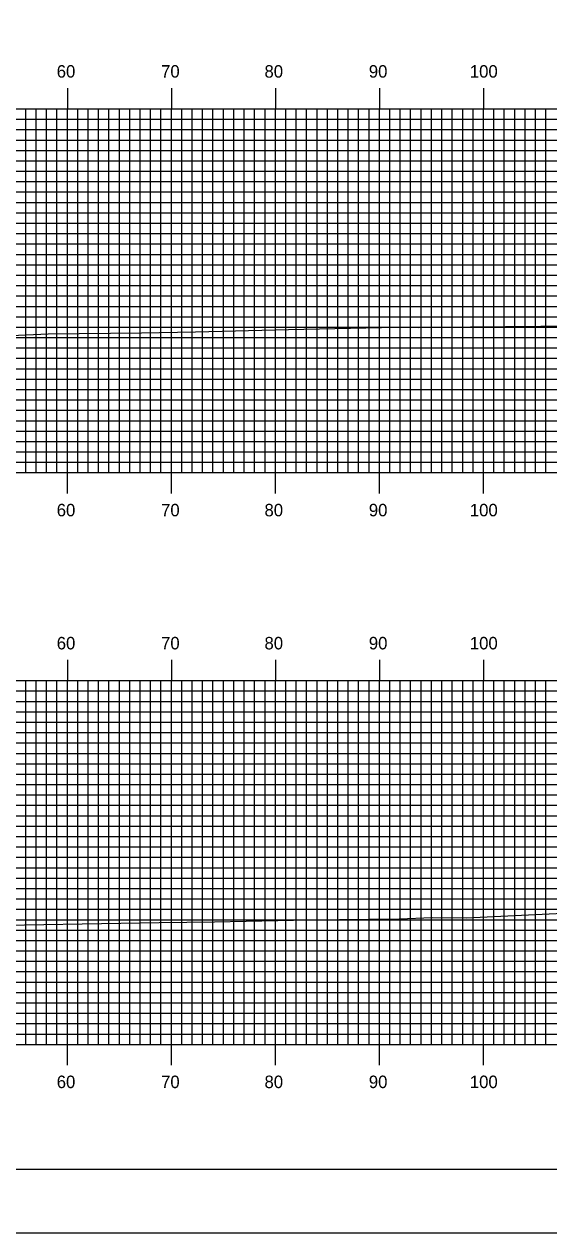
# Model space of a CAD drawing. Extents: x 1760610 to 1760954, y 442591 to 442811.
# Drawn here: x 1760832.1 to 1760882.5, y 442590.5 to 442706.8 of the extents above; entities that cross this region are included whole.
import ezdxf

# ---------------------------------------------------------------- set-up
doc = ezdxf.new("R2010")
doc.units = 0
for name, color, linetype in [('BORDER', 7, 'Continuous'), ('H_V ANNOTATION', 7, 'Continuous'), ('MAJOR', 7, 'Continuous'), ('MINOR', 7, 'Continuous'), ('PLOT BOUNDARY', 7, 'Continuous'), ('S_Roadway_Centerline', 7, 'Continuous')]:
    doc.layers.add(name, color=color, linetype=linetype)

msp = doc.modelspace()

# ---------------------------------------------------------------- linework, layer by layer
at = {"layer": 'BORDER'}
msp.add_lwpolyline([(1760626.61, 442596.67), (1760946.61, 442596.67), (1760946.61, 442806.67), (1760626.61, 442806.67)], close=True, dxfattribs=at)
at = {"layer": 'MAJOR'}
for p, q in [((1760836.21, 442700.67), (1760836.21, 442698.67)), ((1760846.21, 442700.67), (1760846.21, 442698.67)), ((1760856.21, 442700.67), (1760856.21, 442698.67)), ((1760866.21, 442700.67), (1760866.21, 442698.67)), ((1760876.21, 442700.67), (1760876.21, 442698.67)), ((1760636.21, 442698.67), (1760916.21, 442698.67)), ((1760636.21, 442698.67), (1760916.21, 442698.67)), ((1760836.21, 442663.67), (1760836.21, 442698.67)), ((1760846.21, 442663.67), (1760846.21, 442698.67)), ((1760856.21, 442663.67), (1760856.21, 442698.67)), ((1760866.21, 442663.67), (1760866.21, 442698.67)), ((1760876.21, 442663.67), (1760876.21, 442698.67)), ((1760636.21, 442693.67), (1760916.21, 442693.67)), ((1760636.21, 442688.67), (1760916.21, 442688.67)), ((1760636.21, 442683.67), (1760916.21, 442683.67)), ((1760636.21, 442678.67), (1760916.21, 442678.67)), ((1760636.21, 442673.67), (1760916.21, 442673.67)), ((1760636.21, 442668.67), (1760916.21, 442668.67)), ((1760636.21, 442663.67), (1760916.21, 442663.67)), ((1760636.21, 442663.67), (1760916.21, 442663.67)), ((1760836.21, 442661.66), (1760836.21, 442663.67)), ((1760846.21, 442661.66), (1760846.21, 442663.67)), ((1760856.21, 442661.66), (1760856.21, 442663.67)), ((1760866.21, 442661.66), (1760866.21, 442663.67)), ((1760876.21, 442661.66), (1760876.21, 442663.67)), ((1760836.21, 442645.67), (1760836.21, 442643.67)), ((1760846.21, 442645.67), (1760846.21, 442643.67)), ((1760856.21, 442645.67), (1760856.21, 442643.67)), ((1760866.21, 442645.67), (1760866.21, 442643.67)), ((1760876.21, 442645.67), (1760876.21, 442643.67)), ((1760636.21, 442643.67), (1760916.21, 442643.67)), ((1760636.21, 442643.67), (1760916.21, 442643.67)), ((1760836.21, 442608.67), (1760836.21, 442643.67)), ((1760846.21, 442608.67), (1760846.21, 442643.67)), ((1760856.21, 442608.67), (1760856.21, 442643.67)), ((1760866.21, 442608.67), (1760866.21, 442643.67)), ((1760876.21, 442608.67), (1760876.21, 442643.67)), ((1760636.21, 442638.67), (1760916.21, 442638.67)), ((1760636.21, 442633.67), (1760916.21, 442633.67)), ((1760636.21, 442628.67), (1760916.21, 442628.67)), ((1760636.21, 442623.67), (1760916.21, 442623.67)), ((1760636.21, 442618.67), (1760916.21, 442618.67)), ((1760636.21, 442613.67), (1760916.21, 442613.67)), ((1760636.21, 442608.67), (1760916.21, 442608.67)), ((1760636.21, 442608.67), (1760916.21, 442608.67)), ((1760836.21, 442606.66), (1760836.21, 442608.67)), ((1760846.21, 442606.66), (1760846.21, 442608.67)), ((1760856.21, 442606.66), (1760856.21, 442608.67)), ((1760866.21, 442606.66), (1760866.21, 442608.67)), ((1760876.21, 442606.66), (1760876.21, 442608.67))]:
    msp.add_line(p, q, dxfattribs=at)
at = {"layer": 'MINOR'}
for p, q in [((1760832.21, 442663.67), (1760832.21, 442698.67)), ((1760833.21, 442663.67), (1760833.21, 442698.67)), ((1760834.21, 442663.67), (1760834.21, 442698.67)), ((1760835.21, 442663.67), (1760835.21, 442698.67)), ((1760837.21, 442663.67), (1760837.21, 442698.67)), ((1760838.21, 442663.67), (1760838.21, 442698.67)), ((1760839.21, 442663.67), (1760839.21, 442698.67)), ((1760840.21, 442663.67), (1760840.21, 442698.67)), ((1760841.21, 442663.67), (1760841.21, 442698.67)), ((1760842.21, 442663.67), (1760842.21, 442698.67)), ((1760843.21, 442663.67), (1760843.21, 442698.67)), ((1760844.21, 442663.67), (1760844.21, 442698.67)), ((1760845.21, 442663.67), (1760845.21, 442698.67)), ((1760847.21, 442663.67), (1760847.21, 442698.67)), ((1760848.21, 442663.67), (1760848.21, 442698.67)), ((1760849.21, 442663.67), (1760849.21, 442698.67)), ((1760850.21, 442663.67), (1760850.21, 442698.67)), ((1760851.21, 442663.67), (1760851.21, 442698.67)), ((1760852.21, 442663.67), (1760852.21, 442698.67)), ((1760853.21, 442663.67), (1760853.21, 442698.67)), ((1760854.21, 442663.67), (1760854.21, 442698.67)), ((1760855.21, 442663.67), (1760855.21, 442698.67)), ((1760857.21, 442663.67), (1760857.21, 442698.67)), ((1760858.21, 442663.67), (1760858.21, 442698.67)), ((1760859.21, 442663.67), (1760859.21, 442698.67)), ((1760860.21, 442663.67), (1760860.21, 442698.67)), ((1760861.21, 442663.67), (1760861.21, 442698.67)), ((1760862.21, 442663.67), (1760862.21, 442698.67)), ((1760863.21, 442663.67), (1760863.21, 442698.67)), ((1760864.21, 442663.67), (1760864.21, 442698.67)), ((1760865.21, 442663.67), (1760865.21, 442698.67)), ((1760867.21, 442663.67), (1760867.21, 442698.67)), ((1760868.21, 442663.67), (1760868.21, 442698.67)), ((1760869.21, 442663.67), (1760869.21, 442698.67)), ((1760870.21, 442663.67), (1760870.21, 442698.67)), ((1760871.21, 442663.67), (1760871.21, 442698.67)), ((1760872.21, 442663.67), (1760872.21, 442698.67)), ((1760873.21, 442663.67), (1760873.21, 442698.67)), ((1760874.21, 442663.67), (1760874.21, 442698.67)), ((1760875.21, 442663.67), (1760875.21, 442698.67)), ((1760877.21, 442663.67), (1760877.21, 442698.67)), ((1760878.21, 442663.67), (1760878.21, 442698.67)), ((1760879.21, 442663.67), (1760879.21, 442698.67)), ((1760880.21, 442663.67), (1760880.21, 442698.67)), ((1760881.21, 442663.67), (1760881.21, 442698.67)), ((1760882.21, 442663.67), (1760882.21, 442698.67)), ((1760636.21, 442697.67), (1760916.21, 442697.67)), ((1760636.21, 442696.67), (1760916.21, 442696.67)), ((1760636.21, 442695.67), (1760916.21, 442695.67)), ((1760636.21, 442694.67), (1760916.21, 442694.67)), ((1760636.21, 442692.67), (1760916.21, 442692.67)), ((1760636.21, 442691.67), (1760916.21, 442691.67)), ((1760636.21, 442690.67), (1760916.21, 442690.67)), ((1760636.21, 442689.67), (1760916.21, 442689.67)), ((1760636.21, 442687.67), (1760916.21, 442687.67)), ((1760636.21, 442686.67), (1760916.21, 442686.67)), ((1760636.21, 442685.67), (1760916.21, 442685.67)), ((1760636.21, 442684.67), (1760916.21, 442684.67)), ((1760636.21, 442682.67), (1760916.21, 442682.67)), ((1760636.21, 442681.67), (1760916.21, 442681.67)), ((1760636.21, 442680.67), (1760916.21, 442680.67)), ((1760636.21, 442679.67), (1760916.21, 442679.67)), ((1760636.21, 442677.67), (1760916.21, 442677.67)), ((1760636.21, 442676.67), (1760916.21, 442676.67)), ((1760636.21, 442675.67), (1760916.21, 442675.67)), ((1760636.21, 442674.67), (1760916.21, 442674.67)), ((1760636.21, 442672.67), (1760916.21, 442672.67)), ((1760636.21, 442671.67), (1760916.21, 442671.67)), ((1760636.21, 442670.67), (1760916.21, 442670.67)), ((1760636.21, 442669.67), (1760916.21, 442669.67)), ((1760636.21, 442667.67), (1760916.21, 442667.67)), ((1760636.21, 442666.67), (1760916.21, 442666.67)), ((1760636.21, 442665.67), (1760916.21, 442665.67)), ((1760636.21, 442664.67), (1760916.21, 442664.67)), ((1760832.21, 442608.67), (1760832.21, 442643.67)), ((1760833.21, 442608.67), (1760833.21, 442643.67)), ((1760834.21, 442608.67), (1760834.21, 442643.67)), ((1760835.21, 442608.67), (1760835.21, 442643.67)), ((1760837.21, 442608.67), (1760837.21, 442643.67)), ((1760838.21, 442608.67), (1760838.21, 442643.67)), ((1760839.21, 442608.67), (1760839.21, 442643.67)), ((1760840.21, 442608.67), (1760840.21, 442643.67)), ((1760841.21, 442608.67), (1760841.21, 442643.67)), ((1760842.21, 442608.67), (1760842.21, 442643.67)), ((1760843.21, 442608.67), (1760843.21, 442643.67)), ((1760844.21, 442608.67), (1760844.21, 442643.67)), ((1760845.21, 442608.67), (1760845.21, 442643.67)), ((1760847.21, 442608.67), (1760847.21, 442643.67)), ((1760848.21, 442608.67), (1760848.21, 442643.67)), ((1760849.21, 442608.67), (1760849.21, 442643.67)), ((1760850.21, 442608.67), (1760850.21, 442643.67)), ((1760851.21, 442608.67), (1760851.21, 442643.67)), ((1760852.21, 442608.67), (1760852.21, 442643.67)), ((1760853.21, 442608.67), (1760853.21, 442643.67)), ((1760854.21, 442608.67), (1760854.21, 442643.67)), ((1760855.21, 442608.67), (1760855.21, 442643.67)), ((1760857.21, 442608.67), (1760857.21, 442643.67)), ((1760858.21, 442608.67), (1760858.21, 442643.67)), ((1760859.21, 442608.67), (1760859.21, 442643.67)), ((1760860.21, 442608.67), (1760860.21, 442643.67)), ((1760861.21, 442608.67), (1760861.21, 442643.67)), ((1760862.21, 442608.67), (1760862.21, 442643.67)), ((1760863.21, 442608.67), (1760863.21, 442643.67)), ((1760864.21, 442608.67), (1760864.21, 442643.67)), ((1760865.21, 442608.67), (1760865.21, 442643.67)), ((1760867.21, 442608.67), (1760867.21, 442643.67)), ((1760868.21, 442608.67), (1760868.21, 442643.67)), ((1760869.21, 442608.67), (1760869.21, 442643.67)), ((1760870.21, 442608.67), (1760870.21, 442643.67)), ((1760871.21, 442608.67), (1760871.21, 442643.67)), ((1760872.21, 442608.67), (1760872.21, 442643.67)), ((1760873.21, 442608.67), (1760873.21, 442643.67)), ((1760874.21, 442608.67), (1760874.21, 442643.67)), ((1760875.21, 442608.67), (1760875.21, 442643.67)), ((1760877.21, 442608.67), (1760877.21, 442643.67)), ((1760878.21, 442608.67), (1760878.21, 442643.67)), ((1760879.21, 442608.67), (1760879.21, 442643.67)), ((1760880.21, 442608.67), (1760880.21, 442643.67)), ((1760881.21, 442608.67), (1760881.21, 442643.67)), ((1760882.21, 442608.67), (1760882.21, 442643.67)), ((1760636.21, 442642.67), (1760916.21, 442642.67)), ((1760636.21, 442641.67), (1760916.21, 442641.67)), ((1760636.21, 442640.67), (1760916.21, 442640.67)), ((1760636.21, 442639.67), (1760916.21, 442639.67)), ((1760636.21, 442637.67), (1760916.21, 442637.67)), ((1760636.21, 442636.67), (1760916.21, 442636.67)), ((1760636.21, 442635.67), (1760916.21, 442635.67)), ((1760636.21, 442634.67), (1760916.21, 442634.67)), ((1760636.21, 442632.67), (1760916.21, 442632.67)), ((1760636.21, 442631.67), (1760916.21, 442631.67)), ((1760636.21, 442630.67), (1760916.21, 442630.67)), ((1760636.21, 442629.67), (1760916.21, 442629.67)), ((1760636.21, 442627.67), (1760916.21, 442627.67)), ((1760636.21, 442626.67), (1760916.21, 442626.67)), ((1760636.21, 442625.67), (1760916.21, 442625.67)), ((1760636.21, 442624.67), (1760916.21, 442624.67)), ((1760636.21, 442622.67), (1760916.21, 442622.67)), ((1760636.21, 442621.67), (1760916.21, 442621.67)), ((1760636.21, 442620.67), (1760916.21, 442620.67)), ((1760636.21, 442619.67), (1760916.21, 442619.67)), ((1760636.21, 442617.67), (1760916.21, 442617.67)), ((1760636.21, 442616.67), (1760916.21, 442616.67)), ((1760636.21, 442615.67), (1760916.21, 442615.67)), ((1760636.21, 442614.67), (1760916.21, 442614.67)), ((1760636.21, 442612.67), (1760916.21, 442612.67)), ((1760636.21, 442611.67), (1760916.21, 442611.67)), ((1760636.21, 442610.67), (1760916.21, 442610.67)), ((1760636.21, 442609.67), (1760916.21, 442609.67))]:
    msp.add_line(p, q, dxfattribs=at)
at = {"layer": 'PLOT BOUNDARY'}
msp.add_lwpolyline([(1760610.43, 442590.55), (1760950.43, 442590.55), (1760950.43, 442810.55), (1760610.43, 442810.55)], close=True, dxfattribs=at)
at = {"layer": 'S_Roadway_Centerline'}
for points in [[(1760825.1, 442676.61), (1760834.38, 442677.01), (1760843.33, 442677.12), (1760848.54, 442677.22), (1760857.47, 442677.44), (1760867.89, 442677.68), (1760870, 442677.64), (1760871.58, 442677.67), (1760891.86, 442677.86), (1760893.28, 442677.87), (1760904.39, 442677.81), (1760915.51, 442678.04), (1760916.21, 442678.05)], [(1760826.5, 442620.08), (1760845.03, 442620.4), (1760850.35, 442620.47), (1760859.48, 442620.65), (1760868.11, 442620.76), (1760871.29, 442620.88), (1760874.58, 442620.84), (1760890.48, 442621.63), (1760893.05, 442621.77), (1760897.76, 442621.69), (1760912.42, 442621.53), (1760913.08, 442621.63), (1760916.21, 442621.65)]]:
    msp.add_lwpolyline(points, dxfattribs=at)

# ---------------------------------------------------------------- texts
at = {"layer": 'H_V ANNOTATION'}
for s, p in [('60', (1760835.19, 442701.67)), ('70', (1760845.22, 442701.67)), ('80', (1760855.16, 442701.67)), ('90', (1760865.19, 442701.67)), ('100', (1760874.9, 442701.67)), ('60', (1760835.19, 442659.47)), ('70', (1760845.22, 442659.47)), ('80', (1760855.16, 442659.47)), ('90', (1760865.19, 442659.47)), ('100', (1760874.9, 442659.47)), ('60', (1760835.19, 442646.67)), ('70', (1760845.22, 442646.67)), ('80', (1760855.16, 442646.67)), ('90', (1760865.19, 442646.67)), ('100', (1760874.9, 442646.67)), ('60', (1760835.19, 442604.47)), ('70', (1760845.22, 442604.47)), ('80', (1760855.16, 442604.47)), ('90', (1760865.19, 442604.47)), ('100', (1760874.9, 442604.47))]:
    msp.add_text(s, height=1.2, dxfattribs=at).set_placement(p)

doc.saveas('drawing.dxf')
